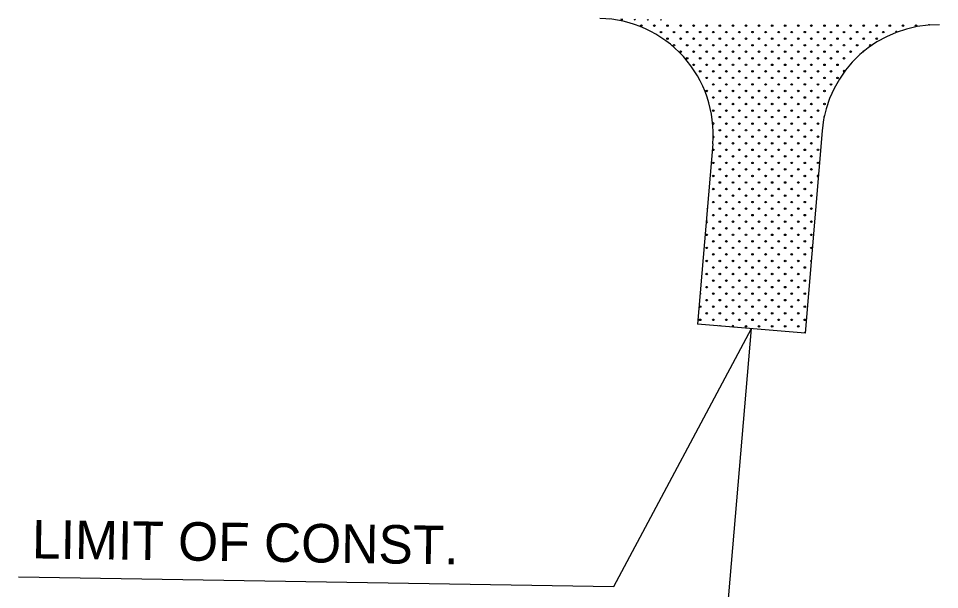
# Model space of a CAD drawing. Extents: x 1681516 to 1684128, y 517931 to 518359.
# Drawn here: x 1684008.3 to 1684127.8, y 518042.3 to 518116.4 of the extents above; entities that cross this region are included whole.
import ezdxf

# ---------------------------------------------------------------- set-up
doc = ezdxf.new("R2010")
doc.units = 0
for name, color, linetype in [('DESIGN - TRANSPORTATION - Driveway Shading', 7, 'Continuous'), ('DESIGN - TRANSPORTATION - Driveways', 7, 'Continuous'), ('DESIGN - TRANSPORTATION - Text', 7, 'Continuous')]:
    doc.layers.add(name, color=color, linetype=linetype)

msp = doc.modelspace()

# ---------------------------------------------------------------- linework, layer by layer
at = {"layer": 'DESIGN - TRANSPORTATION - Driveway Shading'}
for centre in [(1684089.11, 518115.48), (1684089.11, 518115.48), (1684090.8, 518115.48), (1684090.8, 518115.48), (1684091.65, 518114.63), (1684091.65, 518114.63), (1684092.5, 518115.48), (1684092.5, 518115.48), (1684093.35, 518114.63), (1684093.35, 518114.63), (1684094.2, 518115.48), (1684094.2, 518115.48), (1684095.05, 518114.63), (1684095.05, 518114.63), (1684095.89, 518115.48), (1684095.89, 518115.48), (1684096.74, 518114.63), (1684096.74, 518114.63), (1684097.59, 518115.48), (1684097.59, 518115.48), (1684098.44, 518114.63), (1684098.44, 518114.63), (1684099.29, 518115.48), (1684099.29, 518115.48), (1684100.14, 518114.63), (1684100.14, 518114.63), (1684100.99, 518115.48), (1684100.99, 518115.48), (1684101.83, 518114.63), (1684101.83, 518114.63), (1684102.68, 518115.48), (1684102.68, 518115.48), (1684103.53, 518114.63), (1684103.53, 518114.63), (1684104.38, 518115.48), (1684104.38, 518115.48), (1684105.23, 518114.63), (1684105.23, 518114.63), (1684106.08, 518115.48), (1684106.08, 518115.48), (1684106.93, 518114.63), (1684106.93, 518114.63), (1684107.77, 518115.48), (1684107.77, 518115.48), (1684108.62, 518114.63), (1684108.62, 518114.63), (1684109.47, 518115.48), (1684109.47, 518115.48), (1684110.32, 518114.63), (1684110.32, 518114.63), (1684111.17, 518115.48), (1684111.17, 518115.48), (1684112.02, 518114.63), (1684112.02, 518114.63), (1684112.87, 518115.48), (1684112.87, 518115.48), (1684113.71, 518114.63), (1684113.71, 518114.63), (1684114.56, 518115.48), (1684114.56, 518115.48), (1684115.41, 518114.63), (1684115.41, 518114.63), (1684116.26, 518115.48), (1684116.26, 518115.48), (1684117.11, 518114.63), (1684117.11, 518114.63), (1684117.96, 518115.48), (1684117.96, 518115.48), (1684118.81, 518114.63), (1684118.81, 518114.63), (1684119.65, 518115.48), (1684119.65, 518115.48), (1684120.5, 518114.63), (1684120.5, 518114.63), (1684121.35, 518115.48), (1684121.35, 518115.48), (1684123.05, 518115.48), (1684123.05, 518115.48), (1684124.74, 518115.48), (1684124.74, 518115.48), (1684092.5, 518113.78), (1684092.5, 518113.78), (1684094.2, 518113.78), (1684094.2, 518113.78), (1684095.89, 518113.78), (1684095.89, 518113.78), (1684097.59, 518113.78), (1684097.59, 518113.78), (1684099.29, 518113.78), (1684099.29, 518113.78), (1684100.99, 518113.78), (1684100.99, 518113.78), (1684102.68, 518113.78), (1684102.68, 518113.78), (1684104.38, 518113.78), (1684104.38, 518113.78), (1684106.08, 518113.78), (1684106.08, 518113.78), (1684107.77, 518113.78), (1684107.77, 518113.78), (1684109.47, 518113.78), (1684109.47, 518113.78), (1684111.17, 518113.78), (1684111.17, 518113.78), (1684112.87, 518113.78), (1684112.87, 518113.78), (1684114.56, 518113.78), (1684114.56, 518113.78), (1684116.26, 518113.78), (1684116.26, 518113.78), (1684117.96, 518113.78), (1684117.96, 518113.78), (1684119.65, 518113.78), (1684119.65, 518113.78), (1684093.35, 518112.93), (1684093.35, 518112.93), (1684095.05, 518112.93), (1684095.05, 518112.93), (1684096.74, 518112.93), (1684096.74, 518112.93), (1684098.44, 518112.93), (1684098.44, 518112.93), (1684100.14, 518112.93), (1684100.14, 518112.93), (1684101.83, 518112.93), (1684101.83, 518112.93), (1684103.53, 518112.93), (1684103.53, 518112.93), (1684105.23, 518112.93), (1684105.23, 518112.93), (1684106.93, 518112.93), (1684106.93, 518112.93), (1684108.62, 518112.93), (1684108.62, 518112.93), (1684110.32, 518112.93), (1684110.32, 518112.93), (1684112.02, 518112.93), (1684112.02, 518112.93), (1684113.71, 518112.93), (1684113.71, 518112.93), (1684115.41, 518112.93), (1684115.41, 518112.93), (1684117.11, 518112.93), (1684117.11, 518112.93), (1684118.81, 518112.93), (1684118.81, 518112.93), (1684094.2, 518112.08), (1684094.2, 518112.08), (1684095.05, 518111.23), (1684095.05, 518111.23), (1684095.89, 518112.08), (1684095.89, 518112.08), (1684096.74, 518111.23), (1684096.74, 518111.23), (1684097.59, 518112.08), (1684097.59, 518112.08), (1684098.44, 518111.23), (1684098.44, 518111.23), (1684099.29, 518112.08), (1684099.29, 518112.08), (1684100.14, 518111.23), (1684100.14, 518111.23), (1684100.99, 518112.08), (1684100.99, 518112.08), (1684101.83, 518111.23), (1684101.83, 518111.23), (1684102.68, 518112.08), (1684102.68, 518112.08), (1684103.53, 518111.23), (1684103.53, 518111.23), (1684104.38, 518112.08), (1684104.38, 518112.08), (1684105.23, 518111.23), (1684105.23, 518111.23), (1684106.08, 518112.08), (1684106.08, 518112.08), (1684106.93, 518111.23), (1684106.93, 518111.23), (1684107.77, 518112.08), (1684107.77, 518112.08), (1684108.62, 518111.23), (1684108.62, 518111.23), (1684109.47, 518112.08), (1684109.47, 518112.08), (1684110.32, 518111.23), (1684110.32, 518111.23), (1684111.17, 518112.08), (1684111.17, 518112.08), (1684112.02, 518111.23), (1684112.02, 518111.23), (1684112.87, 518112.08), (1684112.87, 518112.08), (1684113.71, 518111.23), (1684113.71, 518111.23), (1684114.56, 518112.08), (1684114.56, 518112.08), (1684115.41, 518111.23), (1684115.41, 518111.23), (1684116.26, 518112.08), (1684116.26, 518112.08), (1684095.89, 518110.38), (1684095.89, 518110.38), (1684097.59, 518110.38), (1684097.59, 518110.38), (1684099.29, 518110.38), (1684099.29, 518110.38), (1684100.99, 518110.38), (1684100.99, 518110.38), (1684102.68, 518110.38), (1684102.68, 518110.38), (1684104.38, 518110.38), (1684104.38, 518110.38), (1684106.08, 518110.38), (1684106.08, 518110.38), (1684107.77, 518110.38), (1684107.77, 518110.38), (1684109.47, 518110.38), (1684109.47, 518110.38), (1684111.17, 518110.38), (1684111.17, 518110.38), (1684112.87, 518110.38), (1684112.87, 518110.38), (1684114.56, 518110.38), (1684114.56, 518110.38), (1684096.74, 518109.54), (1684096.74, 518109.54), (1684097.59, 518108.69), (1684097.59, 518108.69), (1684098.44, 518109.54), (1684098.44, 518109.54), (1684099.29, 518108.69), (1684099.29, 518108.69), (1684100.14, 518109.54), (1684100.14, 518109.54), (1684100.99, 518108.69), (1684100.99, 518108.69), (1684101.83, 518109.54), (1684101.83, 518109.54), (1684102.68, 518108.69), (1684102.68, 518108.69), (1684103.53, 518109.54), (1684103.53, 518109.54), (1684104.38, 518108.69), (1684104.38, 518108.69), (1684105.23, 518109.54), (1684105.23, 518109.54), (1684106.08, 518108.69), (1684106.08, 518108.69), (1684106.93, 518109.54), (1684106.93, 518109.54), (1684107.77, 518108.69), (1684107.77, 518108.69), (1684108.62, 518109.54), (1684108.62, 518109.54), (1684109.47, 518108.69), (1684109.47, 518108.69), (1684110.32, 518109.54), (1684110.32, 518109.54), (1684111.17, 518108.69), (1684111.17, 518108.69), (1684112.02, 518109.54), (1684112.02, 518109.54), (1684112.87, 518108.69), (1684112.87, 518108.69), (1684113.71, 518109.54), (1684113.71, 518109.54), (1684114.56, 518108.69), (1684114.56, 518108.69), (1684098.44, 518107.84), (1684098.44, 518107.84), (1684100.14, 518107.84), (1684100.14, 518107.84), (1684101.83, 518107.84), (1684101.83, 518107.84), (1684103.53, 518107.84), (1684103.53, 518107.84), (1684105.23, 518107.84), (1684105.23, 518107.84), (1684106.93, 518107.84), (1684106.93, 518107.84), (1684108.62, 518107.84), (1684108.62, 518107.84), (1684110.32, 518107.84), (1684110.32, 518107.84), (1684112.02, 518107.84), (1684112.02, 518107.84), (1684113.71, 518107.84), (1684113.71, 518107.84), (1684097.59, 518106.99), (1684097.59, 518106.99), (1684098.44, 518106.14), (1684098.44, 518106.14), (1684099.29, 518106.99), (1684099.29, 518106.99), (1684100.14, 518106.14), (1684100.14, 518106.14), (1684100.99, 518106.99), (1684100.99, 518106.99), (1684101.83, 518106.14), (1684101.83, 518106.14), (1684102.68, 518106.99), (1684102.68, 518106.99), (1684103.53, 518106.14), (1684103.53, 518106.14), (1684104.38, 518106.99), (1684104.38, 518106.99), (1684105.23, 518106.14), (1684105.23, 518106.14), (1684106.08, 518106.99), (1684106.08, 518106.99), (1684106.93, 518106.14), (1684106.93, 518106.14), (1684107.77, 518106.99), (1684107.77, 518106.99), (1684108.62, 518106.14), (1684108.62, 518106.14), (1684109.47, 518106.99), (1684109.47, 518106.99), (1684110.32, 518106.14), (1684110.32, 518106.14), (1684111.17, 518106.99), (1684111.17, 518106.99), (1684112.02, 518106.14), (1684112.02, 518106.14), (1684112.87, 518106.99), (1684112.87, 518106.99), (1684099.29, 518105.29), (1684099.29, 518105.29), (1684100.99, 518105.29), (1684100.99, 518105.29), (1684102.68, 518105.29), (1684102.68, 518105.29), (1684104.38, 518105.29), (1684104.38, 518105.29), (1684106.08, 518105.29), (1684106.08, 518105.29), (1684107.77, 518105.29), (1684107.77, 518105.29), (1684109.47, 518105.29), (1684109.47, 518105.29), (1684111.17, 518105.29), (1684111.17, 518105.29), (1684112.87, 518105.29), (1684112.87, 518105.29), (1684098.44, 518104.44), (1684098.44, 518104.44), (1684100.14, 518104.44), (1684100.14, 518104.44), (1684101.83, 518104.44), (1684101.83, 518104.44), (1684103.53, 518104.44), (1684103.53, 518104.44), (1684105.23, 518104.44), (1684105.23, 518104.44), (1684106.93, 518104.44), (1684106.93, 518104.44), (1684108.62, 518104.44), (1684108.62, 518104.44), (1684110.32, 518104.44), (1684110.32, 518104.44), (1684112.02, 518104.44), (1684112.02, 518104.44), (1684099.29, 518103.6), (1684099.29, 518103.6), (1684100.14, 518102.75), (1684100.14, 518102.75), (1684100.99, 518103.6), (1684100.99, 518103.6), (1684101.83, 518102.75), (1684101.83, 518102.75), (1684102.68, 518103.6), (1684102.68, 518103.6), (1684103.53, 518102.75), (1684103.53, 518102.75), (1684104.38, 518103.6), (1684104.38, 518103.6), (1684105.23, 518102.75), (1684105.23, 518102.75), (1684106.08, 518103.6), (1684106.08, 518103.6), (1684106.93, 518102.75), (1684106.93, 518102.75), (1684107.77, 518103.6), (1684107.77, 518103.6), (1684108.62, 518102.75), (1684108.62, 518102.75), (1684109.47, 518103.6), (1684109.47, 518103.6), (1684110.32, 518102.75), (1684110.32, 518102.75), (1684111.17, 518103.6), (1684111.17, 518103.6), (1684112.02, 518102.75), (1684112.02, 518102.75), (1684099.29, 518101.9), (1684099.29, 518101.9), (1684100.99, 518101.9), (1684100.99, 518101.9), (1684102.68, 518101.9), (1684102.68, 518101.9), (1684104.38, 518101.9), (1684104.38, 518101.9), (1684106.08, 518101.9), (1684106.08, 518101.9), (1684107.77, 518101.9), (1684107.77, 518101.9), (1684109.47, 518101.9), (1684109.47, 518101.9), (1684111.17, 518101.9), (1684111.17, 518101.9), (1684099.29, 518100.2), (1684099.29, 518100.2), (1684100.14, 518101.05), (1684100.14, 518101.05), (1684100.99, 518100.2), (1684100.99, 518100.2), (1684101.83, 518101.05), (1684101.83, 518101.05), (1684102.68, 518100.2), (1684102.68, 518100.2), (1684103.53, 518101.05), (1684103.53, 518101.05), (1684104.38, 518100.2), (1684104.38, 518100.2), (1684105.23, 518101.05), (1684105.23, 518101.05), (1684106.08, 518100.2), (1684106.08, 518100.2), (1684106.93, 518101.05), (1684106.93, 518101.05), (1684107.77, 518100.2), (1684107.77, 518100.2), (1684108.62, 518101.05), (1684108.62, 518101.05), (1684109.47, 518100.2), (1684109.47, 518100.2), (1684110.32, 518101.05), (1684110.32, 518101.05), (1684111.17, 518100.2), (1684111.17, 518100.2), (1684112.02, 518101.05), (1684112.02, 518101.05), (1684098.44, 518099.35), (1684098.44, 518099.35), (1684100.14, 518099.35), (1684100.14, 518099.35), (1684101.83, 518099.35), (1684101.83, 518099.35), (1684103.53, 518099.35), (1684103.53, 518099.35), (1684105.23, 518099.35), (1684105.23, 518099.35), (1684106.93, 518099.35), (1684106.93, 518099.35), (1684108.62, 518099.35), (1684108.62, 518099.35), (1684110.32, 518099.35), (1684110.32, 518099.35), (1684112.02, 518099.35), (1684112.02, 518099.35), (1684099.29, 518098.5), (1684099.29, 518098.5), (1684100.99, 518098.5), (1684100.99, 518098.5), (1684102.68, 518098.5), (1684102.68, 518098.5), (1684104.38, 518098.5), (1684104.38, 518098.5), (1684106.08, 518098.5), (1684106.08, 518098.5), (1684107.77, 518098.5), (1684107.77, 518098.5), (1684109.47, 518098.5), (1684109.47, 518098.5), (1684111.17, 518098.5), (1684111.17, 518098.5), (1684098.44, 518097.66), (1684098.44, 518097.66), (1684099.29, 518096.81), (1684099.29, 518096.81), (1684100.14, 518097.66), (1684100.14, 518097.66), (1684100.99, 518096.81), (1684100.99, 518096.81), (1684101.83, 518097.66), (1684101.83, 518097.66), (1684102.68, 518096.81), (1684102.68, 518096.81), (1684103.53, 518097.66), (1684103.53, 518097.66), (1684104.38, 518096.81), (1684104.38, 518096.81), (1684105.23, 518097.66), (1684105.23, 518097.66), (1684106.08, 518096.81), (1684106.08, 518096.81), (1684106.93, 518097.66), (1684106.93, 518097.66), (1684107.77, 518096.81), (1684107.77, 518096.81), (1684108.62, 518097.66), (1684108.62, 518097.66), (1684109.47, 518096.81), (1684109.47, 518096.81), (1684110.32, 518097.66), (1684110.32, 518097.66), (1684111.17, 518096.81), (1684111.17, 518096.81), (1684112.02, 518097.66), (1684112.02, 518097.66), (1684098.44, 518095.96), (1684098.44, 518095.96), (1684100.14, 518095.96), (1684100.14, 518095.96), (1684101.83, 518095.96), (1684101.83, 518095.96), (1684103.53, 518095.96), (1684103.53, 518095.96), (1684105.23, 518095.96), (1684105.23, 518095.96), (1684106.93, 518095.96), (1684106.93, 518095.96), (1684108.62, 518095.96), (1684108.62, 518095.96), (1684110.32, 518095.96), (1684110.32, 518095.96), (1684098.44, 518094.26), (1684098.44, 518094.26), (1684099.29, 518095.11), (1684099.29, 518095.11), (1684100.14, 518094.26), (1684100.14, 518094.26), (1684100.99, 518095.11), (1684100.99, 518095.11), (1684101.83, 518094.26), (1684101.83, 518094.26), (1684102.68, 518095.11), (1684102.68, 518095.11), (1684103.53, 518094.26), (1684103.53, 518094.26), (1684104.38, 518095.11), (1684104.38, 518095.11), (1684105.23, 518094.26), (1684105.23, 518094.26), (1684106.08, 518095.11), (1684106.08, 518095.11), (1684106.93, 518094.26), (1684106.93, 518094.26), (1684107.77, 518095.11), (1684107.77, 518095.11), (1684108.62, 518094.26), (1684108.62, 518094.26), (1684109.47, 518095.11), (1684109.47, 518095.11), (1684110.32, 518094.26), (1684110.32, 518094.26), (1684111.17, 518095.11), (1684111.17, 518095.11), (1684099.29, 518093.41), (1684099.29, 518093.41), (1684100.99, 518093.41), (1684100.99, 518093.41), (1684102.68, 518093.41), (1684102.68, 518093.41), (1684104.38, 518093.41), (1684104.38, 518093.41), (1684106.08, 518093.41), (1684106.08, 518093.41), (1684107.77, 518093.41), (1684107.77, 518093.41), (1684109.47, 518093.41), (1684109.47, 518093.41), (1684111.17, 518093.41), (1684111.17, 518093.41), (1684098.44, 518092.57), (1684098.44, 518092.57), (1684100.14, 518092.57), (1684100.14, 518092.57), (1684101.83, 518092.57), (1684101.83, 518092.57), (1684103.53, 518092.57), (1684103.53, 518092.57), (1684105.23, 518092.57), (1684105.23, 518092.57), (1684106.93, 518092.57), (1684106.93, 518092.57), (1684108.62, 518092.57), (1684108.62, 518092.57), (1684110.32, 518092.57), (1684110.32, 518092.57), (1684098.44, 518090.87), (1684098.44, 518090.87), (1684099.29, 518091.72), (1684099.29, 518091.72), (1684100.14, 518090.87), (1684100.14, 518090.87), (1684100.99, 518091.72), (1684100.99, 518091.72), (1684101.83, 518090.87), (1684101.83, 518090.87), (1684102.68, 518091.72), (1684102.68, 518091.72), (1684103.53, 518090.87), (1684103.53, 518090.87), (1684104.38, 518091.72), (1684104.38, 518091.72), (1684105.23, 518090.87), (1684105.23, 518090.87), (1684106.08, 518091.72), (1684106.08, 518091.72), (1684106.93, 518090.87), (1684106.93, 518090.87), (1684107.77, 518091.72), (1684107.77, 518091.72), (1684108.62, 518090.87), (1684108.62, 518090.87), (1684109.47, 518091.72), (1684109.47, 518091.72), (1684110.32, 518090.87), (1684110.32, 518090.87), (1684111.17, 518091.72), (1684111.17, 518091.72), (1684099.29, 518090.02), (1684099.29, 518090.02), (1684100.99, 518090.02), (1684100.99, 518090.02), (1684102.68, 518090.02), (1684102.68, 518090.02), (1684104.38, 518090.02), (1684104.38, 518090.02), (1684106.08, 518090.02), (1684106.08, 518090.02), (1684107.77, 518090.02), (1684107.77, 518090.02), (1684109.47, 518090.02), (1684109.47, 518090.02), (1684111.17, 518090.02), (1684111.17, 518090.02), (1684097.59, 518088.32), (1684097.59, 518088.32), (1684098.44, 518089.17), (1684098.44, 518089.17), (1684099.29, 518088.32), (1684099.29, 518088.32), (1684100.14, 518089.17), (1684100.14, 518089.17), (1684100.99, 518088.32), (1684100.99, 518088.32), (1684101.83, 518089.17), (1684101.83, 518089.17), (1684102.68, 518088.32), (1684102.68, 518088.32), (1684103.53, 518089.17), (1684103.53, 518089.17), (1684104.38, 518088.32), (1684104.38, 518088.32), (1684105.23, 518089.17), (1684105.23, 518089.17), (1684106.08, 518088.32), (1684106.08, 518088.32), (1684106.93, 518089.17), (1684106.93, 518089.17), (1684107.77, 518088.32), (1684107.77, 518088.32), (1684108.62, 518089.17), (1684108.62, 518089.17), (1684109.47, 518088.32), (1684109.47, 518088.32), (1684110.32, 518089.17), (1684110.32, 518089.17), (1684111.17, 518088.32), (1684111.17, 518088.32), (1684098.44, 518087.47), (1684098.44, 518087.47), (1684100.14, 518087.47), (1684100.14, 518087.47), (1684101.83, 518087.47), (1684101.83, 518087.47), (1684103.53, 518087.47), (1684103.53, 518087.47), (1684105.23, 518087.47), (1684105.23, 518087.47), (1684106.93, 518087.47), (1684106.93, 518087.47), (1684108.62, 518087.47), (1684108.62, 518087.47), (1684110.32, 518087.47), (1684110.32, 518087.47), (1684097.59, 518086.63), (1684097.59, 518086.63), (1684099.29, 518086.63), (1684099.29, 518086.63), (1684100.99, 518086.63), (1684100.99, 518086.63), (1684102.68, 518086.63), (1684102.68, 518086.63), (1684104.38, 518086.63), (1684104.38, 518086.63), (1684106.08, 518086.63), (1684106.08, 518086.63), (1684107.77, 518086.63), (1684107.77, 518086.63), (1684109.47, 518086.63), (1684109.47, 518086.63), (1684111.17, 518086.63), (1684111.17, 518086.63), (1684097.59, 518084.93), (1684097.59, 518084.93), (1684098.44, 518085.78), (1684098.44, 518085.78), (1684099.29, 518084.93), (1684099.29, 518084.93), (1684100.14, 518085.78), (1684100.14, 518085.78), (1684100.99, 518084.93), (1684100.99, 518084.93), (1684101.83, 518085.78), (1684101.83, 518085.78), (1684102.68, 518084.93), (1684102.68, 518084.93), (1684103.53, 518085.78), (1684103.53, 518085.78), (1684104.38, 518084.93), (1684104.38, 518084.93), (1684105.23, 518085.78), (1684105.23, 518085.78), (1684106.08, 518084.93), (1684106.08, 518084.93), (1684106.93, 518085.78), (1684106.93, 518085.78), (1684107.77, 518084.93), (1684107.77, 518084.93), (1684108.62, 518085.78), (1684108.62, 518085.78), (1684109.47, 518084.93), (1684109.47, 518084.93), (1684110.32, 518085.78), (1684110.32, 518085.78), (1684098.44, 518084.08), (1684098.44, 518084.08), (1684100.14, 518084.08), (1684100.14, 518084.08), (1684101.83, 518084.08), (1684101.83, 518084.08), (1684103.53, 518084.08), (1684103.53, 518084.08), (1684105.23, 518084.08), (1684105.23, 518084.08), (1684106.93, 518084.08), (1684106.93, 518084.08), (1684108.62, 518084.08), (1684108.62, 518084.08), (1684110.32, 518084.08), (1684110.32, 518084.08), (1684097.59, 518083.23), (1684097.59, 518083.23), (1684098.44, 518082.38), (1684098.44, 518082.38), (1684099.29, 518083.23), (1684099.29, 518083.23), (1684100.14, 518082.38), (1684100.14, 518082.38), (1684100.99, 518083.23), (1684100.99, 518083.23), (1684101.83, 518082.38), (1684101.83, 518082.38), (1684102.68, 518083.23), (1684102.68, 518083.23), (1684103.53, 518082.38), (1684103.53, 518082.38), (1684104.38, 518083.23), (1684104.38, 518083.23), (1684105.23, 518082.38), (1684105.23, 518082.38), (1684106.08, 518083.23), (1684106.08, 518083.23), (1684106.93, 518082.38), (1684106.93, 518082.38), (1684107.77, 518083.23), (1684107.77, 518083.23), (1684108.62, 518082.38), (1684108.62, 518082.38), (1684109.47, 518083.23), (1684109.47, 518083.23), (1684110.32, 518082.38), (1684110.32, 518082.38), (1684097.59, 518081.53), (1684097.59, 518081.53), (1684099.29, 518081.53), (1684099.29, 518081.53), (1684100.99, 518081.53), (1684100.99, 518081.53), (1684102.68, 518081.53), (1684102.68, 518081.53), (1684104.38, 518081.53), (1684104.38, 518081.53), (1684106.08, 518081.53), (1684106.08, 518081.53), (1684107.77, 518081.53), (1684107.77, 518081.53), (1684109.47, 518081.53), (1684109.47, 518081.53), (1684097.59, 518079.84), (1684097.59, 518079.84), (1684098.44, 518080.69), (1684098.44, 518080.69), (1684099.29, 518079.84), (1684099.29, 518079.84), (1684100.14, 518080.69), (1684100.14, 518080.69), (1684100.99, 518079.84), (1684100.99, 518079.84), (1684101.83, 518080.69), (1684101.83, 518080.69), (1684102.68, 518079.84), (1684102.68, 518079.84), (1684103.53, 518080.69), (1684103.53, 518080.69), (1684104.38, 518079.84), (1684104.38, 518079.84), (1684105.23, 518080.69), (1684105.23, 518080.69), (1684106.08, 518079.84), (1684106.08, 518079.84), (1684106.93, 518080.69), (1684106.93, 518080.69), (1684107.77, 518079.84), (1684107.77, 518079.84), (1684108.62, 518080.69), (1684108.62, 518080.69), (1684109.47, 518079.84), (1684109.47, 518079.84), (1684110.32, 518080.69), (1684110.32, 518080.69), (1684096.74, 518078.99), (1684096.74, 518078.99), (1684098.44, 518078.99), (1684098.44, 518078.99), (1684100.14, 518078.99), (1684100.14, 518078.99), (1684101.83, 518078.99), (1684101.83, 518078.99), (1684103.53, 518078.99), (1684103.53, 518078.99), (1684105.23, 518078.99), (1684105.23, 518078.99), (1684106.93, 518078.99), (1684106.93, 518078.99), (1684108.62, 518078.99), (1684108.62, 518078.99), (1684110.32, 518078.99), (1684110.32, 518078.99), (1684097.59, 518078.14), (1684097.59, 518078.14), (1684099.29, 518078.14), (1684099.29, 518078.14), (1684100.99, 518078.14), (1684100.99, 518078.14), (1684102.68, 518078.14), (1684102.68, 518078.14), (1684104.38, 518078.14), (1684104.38, 518078.14), (1684106.08, 518078.14), (1684106.08, 518078.14), (1684107.77, 518078.14), (1684107.77, 518078.14), (1684109.47, 518078.14), (1684109.47, 518078.14), (1684096.74, 518077.29), (1684096.74, 518077.29), (1684098.44, 518077.29), (1684098.44, 518077.29), (1684100.14, 518077.29), (1684100.14, 518077.29), (1684101.83, 518077.29), (1684101.83, 518077.29), (1684102.68, 518076.44), (1684102.68, 518076.44), (1684103.53, 518077.29), (1684103.53, 518077.29), (1684104.38, 518076.44), (1684104.38, 518076.44), (1684105.23, 518077.29), (1684105.23, 518077.29), (1684106.08, 518076.44), (1684106.08, 518076.44), (1684106.93, 518077.29), (1684106.93, 518077.29), (1684107.77, 518076.44), (1684107.77, 518076.44), (1684108.62, 518077.29), (1684108.62, 518077.29), (1684109.47, 518076.44), (1684109.47, 518076.44), (1684110.32, 518077.29), (1684110.32, 518077.29)]:
    msp.add_circle(centre, 0.1, dxfattribs=at)
for centre, start, end in [((1684084.86, 518116.32), 140.5542, 166.9921), ((1684084.86, 518116.32), 140.5542, 166.9921), ((1684084.86, 518116.32), 2.2358, 37.2525), ((1684084.86, 518116.32), 2.2358, 37.2525), ((1684086.56, 518116.32), 161.7068, 16.0999), ((1684086.56, 518116.32), 161.7068, 16.0999), ((1684088.26, 518116.32), 180.5737, 357.2329), ((1684088.26, 518116.32), 180.5737, 357.2329), ((1684089.96, 518116.32), 199.6325, 338.1742), ((1684089.96, 518116.32), 199.6325, 338.1742), ((1684091.65, 518116.32), 221.6495, 316.1572), ((1684091.65, 518116.32), 221.6495, 316.1572), ((1684122.2, 518114.63), 55.2161, 221.1277), ((1684122.2, 518114.63), 55.2161, 221.1277), ((1684122.2, 518114.63), 2.1413, 55.2161), ((1684122.2, 518114.63), 2.1413, 55.2161), ((1684126.44, 518115.48), 56.6993, 153.2827), ((1684126.44, 518115.48), 56.6993, 153.2827), ((1684126.44, 518115.48), 34.4749, 56.6993), ((1684126.44, 518115.48), 34.4749, 56.6993), ((1684117.11, 518111.23), 117.3752, 149.4417), ((1684117.11, 518111.23), 117.3752, 149.4417), ((1684117.96, 518112.08), 60.2946, 201.0653), ((1684117.96, 518112.08), 60.2946, 201.0653), ((1684116.26, 518110.38), 86.346, 191.381), ((1684116.26, 518110.38), 86.346, 191.381), ((1684115.41, 518109.54), 72.5053, 276.2133), ((1684115.41, 518109.54), 72.5053, 276.2133), ((1684115.41, 518109.54), 12.4083, 72.5053), ((1684115.41, 518109.54), 12.4083, 72.5053), ((1684098.44, 518102.75), 91.0246, 143.8596), ((1684098.44, 518102.75), 91.0246, 143.8596), ((1684098.44, 518102.75), 226.6163, 91.0246), ((1684098.44, 518102.75), 226.6163, 91.0246), ((1684112.87, 518103.6), 100.4756, 236.658), ((1684112.87, 518103.6), 100.4756, 236.658), ((1684098.44, 518101.05), 78.388, 100.0021), ((1684098.44, 518101.05), 258.9468, 78.388), ((1684098.44, 518101.05), 78.388, 100.0021), ((1684098.44, 518101.05), 258.9468, 78.388), ((1684112.02, 518095.96), 51.1582, 299.212), ((1684112.02, 518095.96), 51.1582, 299.212), ((1684112.02, 518094.26), 145.0546, 205.3156), ((1684112.02, 518094.26), 145.0546, 205.3156), ((1684097.59, 518091.72), 312.842, 37.5281), ((1684097.59, 518091.72), 312.842, 37.5281), ((1684097.59, 518090.02), 221.9227, 128.4475), ((1684097.59, 518090.02), 221.9227, 128.4475), ((1684111.17, 518084.93), 99.3144, 251.0557), ((1684111.17, 518084.93), 99.3144, 251.0557), ((1684096.74, 518080.69), 261.483, 56.9406), ((1684096.74, 518080.69), 261.483, 56.9406), ((1684096.74, 518080.69), 56.9406, 88.8871), ((1684096.74, 518080.69), 56.9406, 88.8871), ((1684099.29, 518076.44), 23.6175, 146.7526), ((1684099.29, 518076.44), 23.6175, 146.7526), ((1684100.99, 518076.44), 283.6814, 246.6887), ((1684100.99, 518076.44), 283.6814, 246.6887), ((1684110.32, 518075.59), 63.0581, 194.3065), ((1684110.32, 518075.59), 63.0581, 194.3065)]:
    msp.add_arc(centre, 0.1, start, end, dxfattribs=at)
at = {"layer": 'DESIGN - TRANSPORTATION - Driveways'}
for p, q in [((1684112.57, 518101.83), (1684110.35, 518075.56)), ((1684098.38, 518100.15), (1684096.4, 518076.73)), ((1684110.35, 518075.56), (1684096.4, 518076.73))]:
    msp.add_line(p, q, dxfattribs=at)
for centre, start, end in [((1684083.43, 518101.41), 355.1851, 88.9033), ((1684127.51, 518100.57), 88.9033, 175.1851)]:
    msp.add_arc(centre, 15, start, end, dxfattribs=at)
at = {"layer": 'DESIGN - TRANSPORTATION - Text'}
for p, q in [((1684085.55, 518042.68), (1684103.38, 518076.15)), ((1684094.89, 517975.33), (1684103.38, 518076.15)), ((1684008.29, 518043.92), (1684085.55, 518042.68))]:
    msp.add_line(p, q, dxfattribs=at)

# ---------------------------------------------------------------- texts
msp.add_text('LIMIT OF CONST.', height=5, rotation=359.1713, dxfattribs=at).set_placement((1684010.03, 518046.34))

doc.saveas('drawing.dxf')
